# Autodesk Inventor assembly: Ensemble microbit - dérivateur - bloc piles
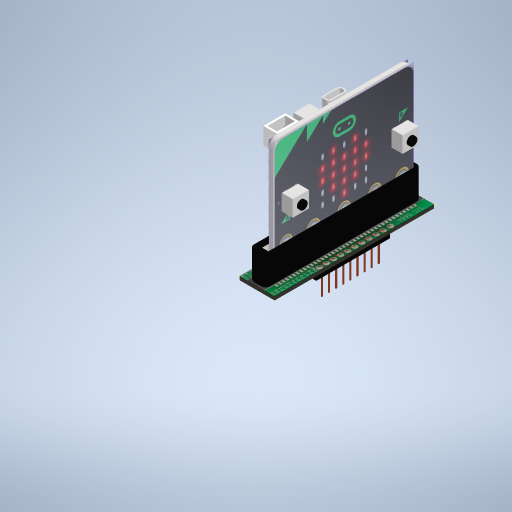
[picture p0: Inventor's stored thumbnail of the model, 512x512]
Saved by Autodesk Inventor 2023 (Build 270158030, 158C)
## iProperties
Created: 2022-12
Part Number: Ensemble microbit - dérivateur - bloc piles
Document SubType Name: Assembly
Designer: ecuenot
Author: ecuenot
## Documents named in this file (3)
- S:\1STI2D1\Documents en consultation\IT\boitier\Inventor indicateur directionnel\Ensemble microbit-connecteur.iam
- S:\1STI2D1\Documents en consultation\IT\boitier\Inventor indicateur directionnel\microbit.ipt
- S:\1STI2D1\Documents en consultation\IT\boitier\Inventor indicateur directionnel\Connecteur-Kitronik.ipt
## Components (2 placed, 2 different names)
1. microbit:1 — Placage:3, Placage:4, Placage:5
2. Connecteur-Kitronik:1 — Placage:3, Placage:4, Placage:5
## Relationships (3: Mate 3)
- Placage:3 [Mate]: microbit:1 ↔ Connecteur-Kitronik:1
- Placage:4 [Mate]: microbit:1 ↔ Connecteur-Kitronik:1
- Placage:5 [Mate]: microbit:1 ↔ Connecteur-Kitronik:1
